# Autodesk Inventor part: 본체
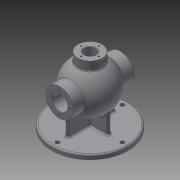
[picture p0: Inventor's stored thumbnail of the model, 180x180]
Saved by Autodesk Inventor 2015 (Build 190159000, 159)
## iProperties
Created: 2020-08
Part Number: 본체
Material: 일반
Document SubType Name: Modeling
Designer: 1019876
Density: 1 g/cm^3
Appearance: 기본값
Author: 1019876
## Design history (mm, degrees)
sketch "스케치1"
  geometry: C1 r 85 at (0, 0); 1 further point
  constraints: 1 centre point, 1 coincident
  dimensions: "d0" = 170 diameter of C1
extrude "돌출1" new body sketch "스케치1" distance "d1" = 10; taper "d2" = 0 deg
sketch "스케치2"
  geometry: L1 (43, 4)-(43, -4); L2 (-43, -4)-(-43, 4); L3 (-43, 4)-(43, -4); L4 (43, 4)-(-43, -4); L5 (-4, 52)-(4, 52); L6 (4, -52)-(-4, -52); L7 (-4, 52)-(4, -52); L8 (4, 52)-(-4, -52); L9 (4, 52)-(4, 4); L10 (4, -4)-(4, -52); L11 (-4, -52)-(-4, -4); L12 (-4, -0.372)-(-4, 0.372); L13 (-4, 4)-(-4, 52); L14 (4, 4)-(43, 4); L15 (-43, 4)-(-4, 4); L16 (43, -4)-(4, -4); L17 (-4, -4)-(-43, -4); C1 r 85 at (0, 0) reference
  constraints: 34 end point, 12 parallel, 4 midpoint, 4 perpendicular, 3 horizontal, 2 point on line
  dimensions: "d3" = 86 distance of L1.end L2.start; "d4" = 8 distance of L1.start L1.end; "d5" = 104 distance of L5.end L6.start; "d6" = 8 distance of L6.start L6.end
extrude "돌출2" join sketch "스케치2" distance "d7" = 75; taper "d8" = 0 deg
sketch "스케치3"
  geometry: L1 (85, 10)-(85, 0) reference; L2 (85, 0)-(-85, 0) reference; L3 (-85, 0)-(-85, 10) reference; L4 (-85, 10)-(-52, 10) reference; L5 (-52, 10)-(-52, 85) reference; L6 (-52, 85)-(52, 85) reference; L7 (52, 85)-(52, 10) reference; L8 (52, 10)-(85, 10) reference; L9 (68, 85)-(-68, 85); L10 (-68, 85)-(-68, 116); L11 (68, 85)-(68, 116); L12 (68, 116)-(42.988, 116); L13 (-42.988, 116)-(-68, 116); A1 r 53 centre (0, 85) between (42.988, 116) and (-42.988, 116); 1 further point
  constraints: 10 end point, 3 parallel, 2 point on circle, 1 centre point, 1 midpoint, 1 vertical
  dimensions: "d9" = 106 diameter of A1; "d12" = 136 distance of L9.start L9.end
revolve "회전1" sketch "스케치3" stored, may be unused: angle "d14" = 90 deg
node "작업 평면1"
sketch "스케치6"
  geometry: C1 r 27 at (0, 0); 1 further point
  constraints: 1 centre point, 1 coincident
  dimensions: "d29" = 54 diameter of C1
extrude "돌출3" join sketch "스케치6" distance "d30" = 54 (= d29); taper "d31" = 0 deg
sketch "스케치4"
  geometry: C1 r 31 at (0, 0) reference; 1 further point
hole "구멍1" sketch "스케치4" at (0, 0) diameter "d15" = 35; stored, may be unused: countersink angle "d19" = 90 deg, drill point angle "d21" = 118 deg; dims "d16" = 6, "d17" = 4, "d18" = 2, "d20" = 8
sketch "스케치5"
  geometry: L1 (42.988, 116)-(68, 116) reference; L2 (68, 116)-(68, 102.5) reference; L3 (68, 102.5)-(-68, 102.5) reference; L4 (-68, 102.5)-(-68, 116) reference; L5 (-68, 116)-(-42.988, 116) reference; L6 (85, 10)-(85, 0) reference; L7 (85, 0)-(-85, 0) reference; L8 (-85, 0)-(-85, 10) reference; L9 (-85, 10)-(-52, 10) reference; L10 (-52, 10)-(-52, 54) reference; L11 (-52, 54)-(-68, 54) reference; L12 (-68, 54)-(-68, 67.5) reference; L13 (-68, 67.5)-(68, 67.5) reference; L14 (68, 67.5)-(68, 54) reference; L15 (68, 54)-(52, 54) reference; L16 (52, 54)-(52, 10) reference; L17 (52, 10)-(85, 10) reference; L18 (-68, 67.5)-(-68, 102.5) reference; L19 (-68, 85)-(68, 85); L20 (50.25, 85)-(50.25, 103.5); L21 (52, 85)-(52, 103.5); L22 (50.25, 103.5)-(52, 103.5); L23 (-27, 130.607)-(-27, 150) reference; L24 (-27, 150)-(27, 150) reference; L25 (27, 150)-(27, 130.607) reference; L26 (68, 102.5)-(68, 67.5) reference; A1 r 43 centre (0, 85) between (43, 85) and (-43, 85); A2 r 53 centre (0, 85) between (-27, 130.607) and (-42.988, 116) reference; A3 r 53 centre (0, 85) between (42.988, 116) and (27, 130.607) reference; 2 further points
  constraints: 8 end point, 5 point on line, 3 parallel, 2 point on circle, 1 centre point, 1 coincident, 1 horizontal, 1 midpoint
  dimensions: "d22" = 86 diameter of A1; "d24" = 1.75 distance between parallel lines of L20 L21; "d84" = 16 distance between parallel lines of L26 L21; "d85" = 18.5 distance between parallel lines of L19 L22
revolve "회전2" sketch "스케치5" stored, may be unused: angle "d27" = 90 deg
sketch "스케치7"
  geometry: C1 r 27 at (0, 0) reference
hole "구멍2" sketch "스케치7" at (0, 0) diameter "d32" = 26; stored, may be unused: countersink angle "d36" = 90 deg, drill point angle "d38" = 118 deg; dims "d33" = 6, "d34" = 4, "d35" = 2, "d37" = 65
sketch "스케치8"
  geometry: C1 r 85 at (0, 0) reference; 1 further point
  constraints: 1 horizontal alignment
  dimensions: "d39" = 72.5 distance of C1.centre point (-72.5, 0)
hole "구멍3" sketch "스케치8" at (-72.5, 0) diameter "d40" = 9; stored, may be unused: countersink angle "d44" = 90 deg, drill point angle "d46" = 118 deg; dims "d41" = 6, "d42" = 4, "d43" = 2, "d45" = 65
sketch "스케치9"
  geometry: C1 r 17.5 at (0, 0) reference; 2 further points
  constraints: 1 vertical alignment
  dimensions: "d50" = 24 distance of point (0, 24) C1.centre
hole "구멍4" sketch "스케치9" at (0, 24) diameter "d51" = 3.242; stored, may be unused: countersink angle "d55" = 90 deg, drill point angle "d57" = 118 deg; dims "d52" = 12, "d53" = 4, "d54" = 2, "d56" = 15
sketch "스케치10"
  geometry: C1 r 13 at (0, 0) reference; 1 further point
  constraints: 1 horizontal alignment
  dimensions: "d61" = 20 distance of C1.centre point (-20, 0)
hole "구멍5" sketch "스케치10" at (-20, 0) diameter "d62" = 3.242; stored, may be unused: countersink angle "d66" = 90 deg, drill point angle "d68" = 118 deg; dims "d63" = 12, "d64" = 4, "d65" = 2, "d67" = 15
node "작업 평면2"
sketch "스케치11"
  geometry: L1 (-27, 0)-(27, 0) reference; 2 further points
  constraints: 1 other
  dimensions: "d73" = 27 horizontal distance of point (0, -9) L1.start; "d74" = 9 vertical distance of point (0, -9) L1.start
feature "엠보싱1" sketch "스케치11" dims "d1" = 10, "d2" = 0, "d75" = 0.5, "d76" = 0
chamfer "모따기1" distance "d77" = 1; stored, may be unused: second distance "d78" = 2, angle "d79" = 45 deg
fillet "모깎기1" dims "d80" = 3
fillet "모깎기2" dims "d81" = 3
fillet "모깎기3" dims "d82" = 3
fillet "모깎기4" dims "d83" = 3
node "솔리드1"
pattern_circular "원형 패턴1" dims angle "d48" = 360 deg
pattern_circular "원형 패턴2" dims angle "d59" = 360 deg
mirror "대칭1"
pattern_circular "원형 패턴3" dims angle "d70" = 360 deg
node "절단 모서리 투영1"
node "절단 모서리 투영2"
other parameters: "d13" = 31, "d25" = 18.5
